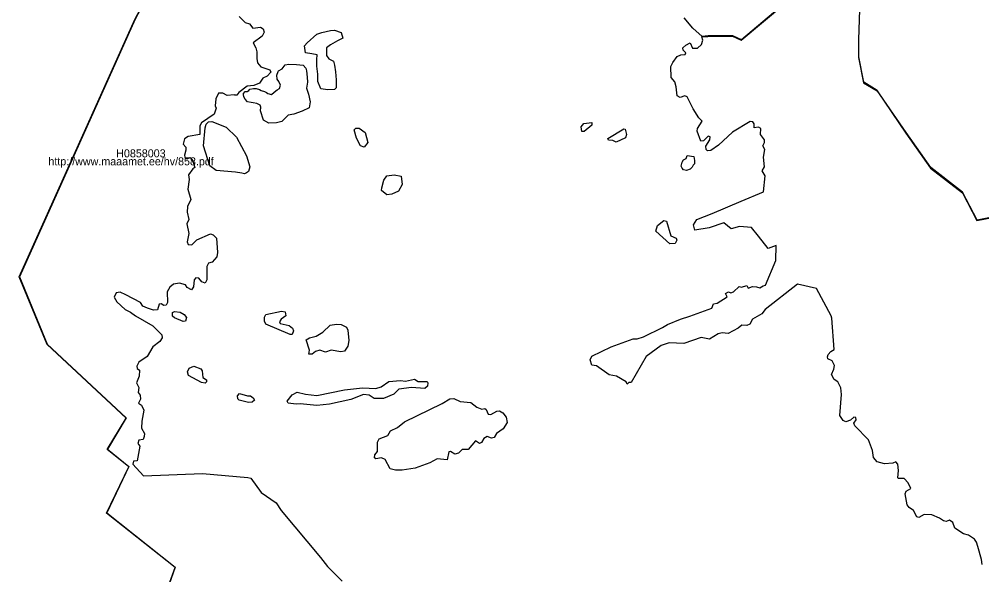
# Model space of a CAD drawing. Extents: x 369010 to 739155, y 6377141 to 6634081.
# Drawn here: x 437921 to 440928, y 6469635 to 6471370 of the extents above; entities that cross this region are included whole.
import ezdxf

# ---------------------------------------------------------------- set-up
doc = ezdxf.new("R2010")
doc.units = 0
for name, color, linetype in [('H_LINK', 7, 'Continuous'), ('H_PIIR', 7, 'Continuous'), ('H_TUNNUS', 7, 'Continuous')]:
    doc.layers.add(name, color=color, linetype=linetype)

msp = doc.modelspace()

# ---------------------------------------------------------------- linework, layer by layer
at = {"layer": 'H_PIIR'}
for points in [[(438583.1538, 6473673.3184), (438677.4538, 6472934.0884), (438685.1037, 6472609.6884), (438787.1737, 6472316.9039), (438282.4239, 6471370.8538), (437921.5138, 6470566.3639), (438008.4139, 6470355.6137), (438255.0238, 6470125.3038), (438196.1538, 6470027.1938), (438263.4339, 6469973.2339), (438194.2538, 6469828.5238), (438408.3038, 6469659.0938), (438375.3739, 6469567.3238)], [(438374.5801, 6469566.53), (438407.51, 6469658.3), (438193.46, 6469827.73), (438262.6401, 6469972.4401), (438195.36, 6470026.4), (438254.23, 6470124.51), (438007.6201, 6470354.8199), (437920.72, 6470565.5701), (438281.6301, 6471370.06), (438786.3825, 6472316.1147)], [(440928.54, 6469667.7947), (440927.28, 6469682.5146), (440915.72, 6469723.3247), (440911.09, 6469737.6347), (440904.78, 6469746.8947), (440885.85, 6469759.0947), (440871.1301, 6469762.8746), (440843.78, 6469781.3946), (440837.47, 6469799.0646), (440827.38, 6469805.7947), (440816.44, 6469801.5846), (440808.2401, 6469803.6946), (440796.0399, 6469812.5346), (440772.06, 6469822.6347), (440747.24, 6469823.0547), (440731.26, 6469813.7947), (440724.95, 6469815.8946), (440714.43, 6469835.6747), (440701.3899, 6469844.9247), (440695.0799, 6469853.7647), (440688.7701, 6469887.8446), (440691.92, 6469896.2647), (440705.81, 6469904.6746), (440697.3899, 6469922.7646), (440685.1899, 6469936.2347), (440667.5201, 6469935.8146), (440664.9999, 6469937.9147), (440667.1, 6469961.4747), (440665.84, 6469980.8346), (440659.11, 6469987.5647), (440650.28, 6469983.7746), (440623.77, 6469981.6747), (440601.0601, 6469988.4046), (440589.7, 6470001.8647), (440586.7501, 6470023.7446), (440573.9199, 6470056.9846), (440531.01, 6470100.7447), (440528.49, 6470109.1647), (440534.8001, 6470119.6847), (440534.38, 6470126.8346), (440527.65, 6470127.6747), (440517.13, 6470117.9947), (440503.25, 6470112.9446), (440494.4101, 6470117.1546), (440484.74, 6470132.3047), (440489.99, 6470198.7747), (440487.05, 6470219.3947), (440477.79, 6470237.4847), (440466.85, 6470245.4747), (440458.4399, 6470261.0447), (440465.17, 6470277.4546), (440467.2701, 6470288.8147), (440460.3301, 6470303.5446), (440446.4501, 6470309.8546), (440445.61, 6470316.1646), (440448.1299, 6470323.7346), (440455.7101, 6470332.5747), (440466.22, 6470338.8847), (440459.49, 6470436.9147), (440457.6, 6470444.0646), (440411.5108, 6470529.713), (440351.8001, 6470542.9346), (440251.04, 6470464.2546), (440240.9399, 6470449.9446), (440211.92, 6470433.5347), (440203.4999, 6470418.3946), (440194.04, 6470413.7646), (440178.48, 6470415.0247), (440167.1199, 6470405.3547), (440135.57, 6470389.3646), (440117.0601, 6470391.0446), (440104.02, 6470387.6746), (440077.0899, 6470370.8446), (440051.01, 6470376.3147), (439997.38, 6470357.8046), (439951.53, 6470359.9146), (439926.28, 6470351.0747), (439879.58, 6470317.4146), (439832.4699, 6470235.7946), (439825.32, 6470236.2147), (439819.43, 6470230.3247), (439816.4801, 6470238.3146), (439787.0929, 6470255.6041), (439763.5331, 6470259.8141), (439724.36, 6470287.9646), (439709.6301, 6470290.0746), (439704.16, 6470306.9046), (439709.6301, 6470318.2647), (439770.2101, 6470346.8747), (439838.57, 6470372.5346), (439851.19, 6470372.5346), (439871.38, 6470378.0046), (439930.79, 6470407.75), (439945.93, 6470417.42), (439986.5701, 6470434.16), (440015.6, 6470443.41), (440084.6601, 6470468.4646), (440089.2901, 6470481.5047), (440101.07, 6470484.0346), (440132.2, 6470503.3847), (440127.57, 6470513.9046), (440136.41, 6470519.3746), (440143.9799, 6470515.5847), (440151.97, 6470518.5346), (440170.0601, 6470536.2047), (440177.21, 6470534.1046), (440193.4, 6470538.7246), (440198.03, 6470530.7346), (440211.91, 6470535.3646), (440223.6899, 6470534.5147), (440234.6299, 6470531.1547), (440244.31, 6470537.8847), (440252.3, 6470539.5646), (440284.5105, 6470616.4965), (440285.5689, 6470664.1216), (440260.1688, 6470654.5966), (440230.5354, 6470692.6967), (440208.3104, 6470720.2134), (440171.2686, 6470723.3884), (440144.8103, 6470715.98), (440121.5269, 6470735.0301), (440076.0184, 6470719.155), (440031.5684, 6470711.7467), (440027.335, 6470728.6801), (440037.9184, 6470744.5551), (440085.5435, 6470763.6051), (440176.5603, 6470801.7052), (440245.99, 6470831.5647), (440250.62, 6470881.6346), (440241.5699, 6470896.7847), (440249.1401, 6470909.8246), (440246.1999, 6470939.2746), (440250.41, 6470964.0946), (440243.2499, 6470975.0346), (440248.72, 6470985.1347), (440248.72, 6470993.5546), (440236.1, 6471009.9647), (440237.79, 6471028.8947), (440230.21, 6471033.5247), (440216.7499, 6471031.4147), (440217.17, 6471043.6146), (440212.97, 6471050.3547), (440204.1301, 6471051.1946), (440148.8201, 6471017.9547), (440105.4901, 6470977.1447), (440081.0899, 6470960.7346), (440070.57, 6470959.4746), (440066.7801, 6470963.2647), (440065.5199, 6470973.7846), (440077.7199, 6470993.9746), (440079.4099, 6471003.6547), (440072.67, 6471005.3347), (440058.37, 6470990.6146), (440050.38, 6470989.3446), (440039.0199, 6471020.4846), (440040.08, 6471029.3146), (440054.38, 6471052.4546), (440044.2801, 6471062.9747), (440025.7699, 6471090.3246), (440007.2599, 6471128.1947), (440000.5301, 6471131.1347), (439984.97, 6471125.6646), (439975.7101, 6471131.5547), (439972.56, 6471158.9047), (439968.35, 6471174.8947), (439957.8301, 6471188.7847), (439956.15, 6471223.2846), (439962.8799, 6471235.0647), (439975.92, 6471253.5746), (439987.28, 6471259.0446), (440000.74, 6471260.7246), (440003.69, 6471265.7746), (439995.2701, 6471273.7746), (439994.0099, 6471281.3446), (440003.69, 6471289.3346), (440017.1499, 6471296.4946), (440023.88, 6471280.0847), (440039.44, 6471280.0847), (440052.06, 6471291.8646), (440056.2699, 6471304.9047), (440053.33, 6471315.0046), (440052.9447, 6471315.3403), (440072.23, 6471316.8101), (440149.3001, 6471317.45), (440176.5001, 6471304.84), (440309.36, 6471416.9899)], [(440310.1538, 6471418.5774), (440177.2939, 6471306.4275), (440150.0939, 6471319.0375), (440073.0238, 6471318.3976), (440053.7385, 6471316.9278), (440024.6738, 6471342.2522), (439997.5338, 6471375.0822)], [(440545.7601, 6471399.35), (440542.55, 6471306.09), (440542.55, 6471251.4299), (440558.62, 6471172.32), (440600.4099, 6471146.6001), (440690.4099, 6471014.75), (440767.56, 6470905.4201), (440867.21, 6470828.24), (440912.21, 6470741.4099), (441043.1201, 6470766.8399)], [(441043.9139, 6470768.4274), (440913.0038, 6470742.9974), (440868.0038, 6470829.8275), (440768.3538, 6470907.0076), (440691.2037, 6471016.3375), (440601.2037, 6471148.1876), (440559.4138, 6471173.9075), (440543.3438, 6471253.0174), (440543.3438, 6471307.6775), (440546.5539, 6471400.9375)], [(438607.91, 6471379.3646), (438626.42, 6471360.0146), (438640.3, 6471355.8046), (438650.8199, 6471342.7647), (438674.8, 6471345.2847), (438683.2101, 6471340.6547), (438685.74, 6471330.5646), (438679.42, 6471317.9347), (438651.03, 6471296.4746), (438660.28, 6471280.9146), (438663.23, 6471268.7046), (438662.81, 6471248.0946), (438665.3301, 6471234.6246), (438675.43, 6471222.0046), (438704.0301, 6471211.9047), (438706.56, 6471204.7546), (438695.1999, 6471192.9746), (438682.16, 6471186.2446), (438671.1487, 6471171.029), (438653.9507, 6471163.7529), (438632.784, 6471161.7686), (438606.87, 6471141.6346), (438600.5599, 6471133.6346), (438593.8201, 6471133.2146), (438592.39, 6471133.85), (438569.9398, 6471132.6103), (438556.38, 6471139.1047), (438542.9199, 6471139.1047), (438534.888, 6471121.4195), (438532.6101, 6471100.4047), (438535.9799, 6471092.4047), (438529.6699, 6471074.3146), (438490.1, 6471047.3447), (438485.05, 6471037.2446), (438484.6299, 6471010.3246), (438448.8982, 6471004.3412), (438436.992, 6470996.4037), (438432.89, 6470980.4447), (438441.2999, 6470971.1847), (438440.8801, 6470961.0846), (438437.1, 6470945.5246), (438437.9399, 6470939.2146), (438445.09, 6470934.5846), (438455.1899, 6470938.5047), (438459.8099, 6470934.1646), (438464.86, 6470921.1147), (438469.0699, 6470907.6546), (438463.18, 6470903.0246), (438449.72, 6470884.5146), (438451.8201, 6470870.2147), (438447.41, 6470839.4946), (438457.0801, 6470807.1046), (438446.1501, 6470786.0647), (438445.73, 6470767.5547), (438450.77, 6470744.8346), (438444.04, 6470731.7947), (438450.35, 6470701.5046), (438444.8801, 6470675.4147), (438448.2499, 6470666.5747), (438460.03, 6470665.7346), (438475.17, 6470681.7247), (438518.5, 6470699.8146), (438526.9101, 6470697.2947), (438536.8, 6470686.7747), (438540.5799, 6470642.1746), (438537.64, 6470627.8747), (438523.76, 6470611.8847), (438511.7699, 6470608.5146), (438507.1399, 6470597.9947), (438507.1399, 6470556.7646), (438501.67, 6470546.2446), (438490.73, 6470550.0347), (438481.48, 6470562.2347), (438472.6401, 6470562.6547), (438466.7599, 6470556.7646), (438465.0699, 6470534.4647), (438459.18, 6470525.6346), (438445.72, 6470532.7847), (438440.2499, 6470541.1946), (438420.9, 6470545.8246), (438402.39, 6470543.3046), (438391.04, 6470533.2046), (438382.6201, 6470519.3246), (438383.89, 6470485.2446), (438380.1, 6470477.2446), (438372.1099, 6470475.9846), (438364.54, 6470481.8747), (438357.8001, 6470480.6146), (438352.34, 6470462.9447), (438339.9301, 6470462.1046), (438321, 6470467.5747), (438307.12, 6470474.3046), (438299.12, 6470485.2446), (438253.2699, 6470509.6447), (438236.0201, 6470518.4747), (438223.8299, 6470516.3746), (438217.5199, 6470502.0747), (438225.0901, 6470487.3446), (438251.17, 6470464.2047), (438267.99, 6470455.7946), (438284.3999, 6470444.0147), (438338.46, 6470412.8747), (438366.22, 6470385.1047), (438367.4899, 6470375.8447), (438360.34, 6470364.0646), (438337.6201, 6470346.8146), (438320.7899, 6470317.3646), (438294.08, 6470298.8546), (438288.19, 6470287.0747), (438289.0299, 6470279.4947), (438296.6001, 6470274.8747), (438295.3399, 6470255.5146), (438286.92, 6470235.3246), (438294.08, 6470219.7546), (438292.39, 6470204.1846), (438298.7, 6470195.7747), (438299.5401, 6470183.9946), (438292.81, 6470170.9547), (438302.9099, 6470165.4846), (438309.64, 6470149.0747), (438303.97, 6470115.4146), (438302.71, 6470093.5346), (438311.96, 6470076.7046), (438311.1201, 6470067.0347), (438307.33, 6470057.3547), (438294.2901, 6470055.2446), (438291.3499, 6470045.5746), (438297.2401, 6470037.1547), (438289.45, 6469991.2946), (438277.25, 6469990.0346), (438275.98, 6469980.3546), (438309.2199, 6469944.1747), (438493.216, 6469951.2974), (438635.03, 6469938.7146), (438643.8599, 6469937.0346), (438676.67, 6469892.4347), (438723.404, 6469860.016), (438739.279, 6469836.2034), (438862.3105, 6469689.3594), (438883.4772, 6469661.5781), (438929.7794, 6469615.2759)]]:
    msp.add_lwpolyline(points, dxfattribs=at)
for points in [[(438819.9771, 6471297.0768), (438850.1397, 6471324.0643), (438866.0147, 6471328.8268), (438893.0023, 6471335.1768), (438905.7023, 6471336.7643), (438926.3398, 6471328.8268), (438931.1023, 6471311.3643), (438915.2273, 6471303.4268), (438893.0023, 6471290.7267), (438880.3022, 6471281.2017), (438880.3022, 6471257.3892), (438888.2398, 6471246.2767), (438902.5273, 6471239.9266), (438905.7023, 6471227.2266), (438908.8773, 6471206.5891), (438910.4648, 6471181.189), (438910.4648, 6471155.789), (438905.7023, 6471151.0265), (438885.0647, 6471149.439), (438862.8397, 6471152.614), (438853.3147, 6471176.4265), (438853.3147, 6471198.6516), (438850.1397, 6471224.0516), (438850.1397, 6471244.6892), (438851.7272, 6471258.9767), (438834.2646, 6471262.1517), (438815.2146, 6471265.3267), (438812.0396, 6471287.5517)], [(438742.1895, 6471215.5849), (438751.7145, 6471227.7558), (438762.827, 6471229.8725), (438786.6395, 6471229.3433), (438807.2771, 6471226.6974), (438816.2729, 6471217.1724), (438817.8604, 6471209.7641), (438819.9771, 6471189.6557), (438821.0355, 6471173.7807), (438817.8604, 6471154.7306), (438824.2105, 6471136.2098), (438830.0313, 6471112.9264), (438826.3271, 6471093.8763), (438804.6313, 6471083.8222), (438778.702, 6471073.768), (438760.7103, 6471071.1221), (438741.1311, 6471051.5429), (438724.1978, 6471046.7804), (438700.3852, 6471045.7221), (438683.981, 6471055.2471), (438674.456, 6471084.8805), (438674.9852, 6471095.993), (438673.3977, 6471101.8139), (438663.3435, 6471107.1055), (438651.7018, 6471109.2222), (438644.8226, 6471110.2805), (438634.2392, 6471112.9264), (438626.3017, 6471120.8639), (438622.0684, 6471127.7431), (438621.0101, 6471135.1514), (438621.0101, 6471138.8556), (438626.3017, 6471144.6765), (438632.6517, 6471145.2056), (438637.9434, 6471147.8515), (438641.1184, 6471152.0848), (438652.7601, 6471153.6723), (438660.6976, 6471153.6723), (438671.281, 6471150.4973), (438676.0435, 6471148.3806), (438687.156, 6471145.2056), (438692.9769, 6471142.0306), (438697.7394, 6471138.8556), (438708.8519, 6471135.1514), (438717.3186, 6471142.5598), (438726.8436, 6471149.9681), (438733.7228, 6471153.6723), (438736.3686, 6471164.2557), (438731.6061, 6471176.4265), (438726.3144, 6471183.3057), (438725.2561, 6471196.0057), (438730.0186, 6471207.1182), (438731.0769, 6471209.2349)], [(438640.6835, 6470909.7263), (438637.208, 6470894.4999), (438630.9189, 6470891.1899), (438624.5378, 6470887.2805), (438615.8066, 6470889.6617), (438596.3597, 6470893.2336), (438535.6377, 6470897.5992), (438516.5876, 6470913.0774), (438496.7438, 6470975.3869), (438501.8257, 6471031.3718), (438504.3083, 6471043.1224), (438512.4179, 6471049.7427), (438522.0171, 6471051.0668), (438567.5307, 6471033.0268), (438599.4731, 6471002.2431), (438630.5878, 6470944.1511)], [(439010.0885, 6470985.5271), (438997.8411, 6470971.1283), (438986.9178, 6470974.9349), (438973.8431, 6470999.4295), (438966.7265, 6471024.5861), (438972.1881, 6471029.7166), (438982.6148, 6471029.7166), (439001.1512, 6471016.9728)], [(439709.6738, 6471048.2193), (439709.1774, 6471039.7786), (439685.6758, 6471019.5872), (439678.3936, 6471019.5872), (439675.9111, 6471034.648), (439684.3517, 6471044.4127)], [(439809.1418, 6471028.3589), (439813.7759, 6471026.7039), (439817.9135, 6471010.3189), (439814.6034, 6470999.7266), (439785.1436, 6470986.6519), (439775.379, 6470991.286), (439761.1456, 6470993.1065), (439758.994, 6470998.0716)], [(440004.1778, 6470935.9122), (440007.3528, 6470944.9081), (440027.9903, 6470941.7331), (440030.6361, 6470929.5622), (440030.107, 6470918.9788), (440025.8736, 6470914.2163), (440023.2278, 6470908.3955), (440016.8778, 6470902.5746), (440005.7653, 6470898.3413), (439996.2402, 6470900.458), (439991.4777, 6470905.7496), (439988.8319, 6470911.0413), (439992.0069, 6470924.2705), (439995.7111, 6470931.6789)], [(439059.8841, 6470868.204), (439069.4091, 6470880.904), (439091.6342, 6470884.079), (439113.8592, 6470879.8456), (439117.0342, 6470854.4456), (439105.3925, 6470833.2789), (439084.2258, 6470823.7539), (439069.4091, 6470821.6372), (439052.4758, 6470835.3956), (439053.5341, 6470843.8622)], [(439952.9647, 6470668.7186), (439909.2717, 6470708.1085), (439914.7333, 6470726.6451), (439934.0972, 6470741.375), (439942.3725, 6470739.3889), (439956.2747, 6470694.3718), (439972.6597, 6470687.0897), (439974.8113, 6470679.973), (439969.3496, 6470669.8772)], [(438440.5892, 6470427.6131), (438432.976, 6470426.2892), (438406.1643, 6470437.7089), (438399.0476, 6470443.5016), (438399.8752, 6470454.4247), (438406.1643, 6470457.4038), (438423.0458, 6470455.2522), (438435.9551, 6470447.8046), (438443.5683, 6470438.8675)], [(438772.9213, 6470385.4097), (438767.1285, 6470385.4097), (438690.9968, 6470417.8484), (438686.6936, 6470427.1167), (438687.1902, 6470439.695), (438690.9968, 6470447.8046), (438740.1514, 6470459.0589), (438751.0747, 6470457.0729), (438753.2263, 6470444.3291), (438738.4964, 6470433.4058), (438733.3658, 6470425.7926), (438736.0138, 6470420.3309), (438764.1496, 6470414.0418), (438774.5763, 6470405.2701), (438777.2243, 6470396.8293)], [(438946.8658, 6470348.8332), (438936.7702, 6470334.1034), (438925.0194, 6470331.6209), (438894.7321, 6470337.0825), (438877.5197, 6470330.7934), (438859.4799, 6470337.0825), (438846.405, 6470332.9448), (438836.3092, 6470324.5042), (438825.717, 6470324.0077), (438827.041, 6470337.0825), (438817.2763, 6470368.6938), (438827.8685, 6470374.9829), (438848.06, 6470380.4446), (438869.0791, 6470393.5193), (438892.2496, 6470414.8693), (438911.6136, 6470417.8484), (438926.6745, 6470417.0209), (438943.0594, 6470409.0767), (438947.6935, 6470399.8085), (438949.845, 6470367.3697)], [(438501.0319, 6470233.6761), (438490.1086, 6470236.1587), (438449.2291, 6470258.0052), (438445.9191, 6470269.4251), (438451.0496, 6470280.3484), (438466.1105, 6470287.134), (438487.957, 6470278.3623), (438492.2602, 6470272.404), (438494.2462, 6470251.7161), (438505.6661, 6470244.2685), (438506.1625, 6470237.4828)], [(439155.5664, 6470246.2207), (439166.9863, 6470238.6077), (439194.6254, 6470239.1041), (439197.2734, 6470235.2974), (439195.9495, 6470224.3742), (439188.0052, 6470217.5886), (439146.2983, 6470220.0711), (439106.7427, 6470215.1061), (439091.1855, 6470199.8796), (439058.7465, 6470185.6462), (439029.9489, 6470185.6462), (439014.0606, 6470196.5695), (438996.6827, 6470198.7211), (438956.2996, 6470182.3362), (438889.767, 6470167.9374), (438850.5426, 6470163.7998), (438798.4088, 6470169.2615), (438785.996, 6470167.9374), (438760.8394, 6470171.744), (438758.1914, 6470178.0332), (438772.9213, 6470197.0661), (438789.3062, 6470205.3412), (438814.9592, 6470199.0521), (438849.8805, 6470195.2456), (438936.7702, 6470213.451), (438992.7106, 6470219.2436), (439035.0795, 6470217.5886), (439051.7955, 6470221.8916), (439075.7935, 6470238.6077), (439111.5423, 6470242.4141), (439127.5963, 6470240.4282)], [(438648.1649, 6470173.9292), (438637.0761, 6470173.4328), (438608.113, 6470181.046), (438603.4789, 6470184.5215), (438602.1548, 6470194.1207), (438608.9405, 6470201.734), (438633.7661, 6470194.1207), (438643.5309, 6470194.1207), (438651.806, 6470188.1627), (438655.2815, 6470181.046)], [(439278.0732, 6470186.1765), (439298.5957, 6470176.0808), (439331.0344, 6470173.4328), (439350.3985, 6470158.3719), (439365.4593, 6470152.0828), (439375.224, 6470154.5653), (439379.8581, 6470151.5862), (439385.3198, 6470137.3528), (439393.926, 6470135.6978), (439412.4623, 6470146.6211), (439420.9031, 6470147.4486), (439430.9989, 6470141.1595), (439441.4256, 6470127.2571), (439444.9011, 6470110.8721), (439432.9848, 6470091.0117), (439411.9659, 6470076.282), (439404.0217, 6470064.5312), (439396.0776, 6470062.0486), (439382.5061, 6470067.5101), (439372.0794, 6470061.2209), (439364.4662, 6470048.1462), (439359.0045, 6470045.1671), (439345.5987, 6470053.6079), (439323.2557, 6470026.2997), (439304.7194, 6470026.2997), (439292.9686, 6470015.3764), (439281.2178, 6470012.3973), (439267.4808, 6470020.0105), (439262.5158, 6470019.5141), (439257.8816, 6469993.8609), (439226.767, 6469997.6675), (439203.5963, 6469985.4201), (439157.9172, 6469968.2077), (439116.7067, 6469961.9185), (439095.6877, 6469962.2497), (439079.6339, 6469966.5527), (439063.7455, 6469995.185), (439052.8222, 6470000.9776), (439034.6168, 6469997.1709), (439030.4792, 6470000.9776), (439031.8031, 6470010.2458), (439040.0784, 6470020.3416), (439040.0784, 6470049.4703), (439044.7126, 6470060.3934), (439072.1863, 6470069.9928), (439080.1304, 6470084.7225), (439101.9768, 6470095.6458), (439124.4855, 6470113.3548), (439241.6623, 6470170.1227), (439265.6603, 6470185.349)]]:
    msp.add_lwpolyline(points, close=True, dxfattribs=at)

# ---------------------------------------------------------------- texts
at = {"layer": 'H_LINK'}
msp.add_text('http://www.maaamet.ee/hv/858.pdf', height=25, rotation=360, dxfattribs=at).set_placement((438011.8106, 6470914.1206))
at = {"layer": 'H_TUNNUS'}
msp.add_text('H0858003', height=25, rotation=360, dxfattribs=at).set_placement((438223.6651, 6470939.1206))

doc.saveas('drawing.dxf')
